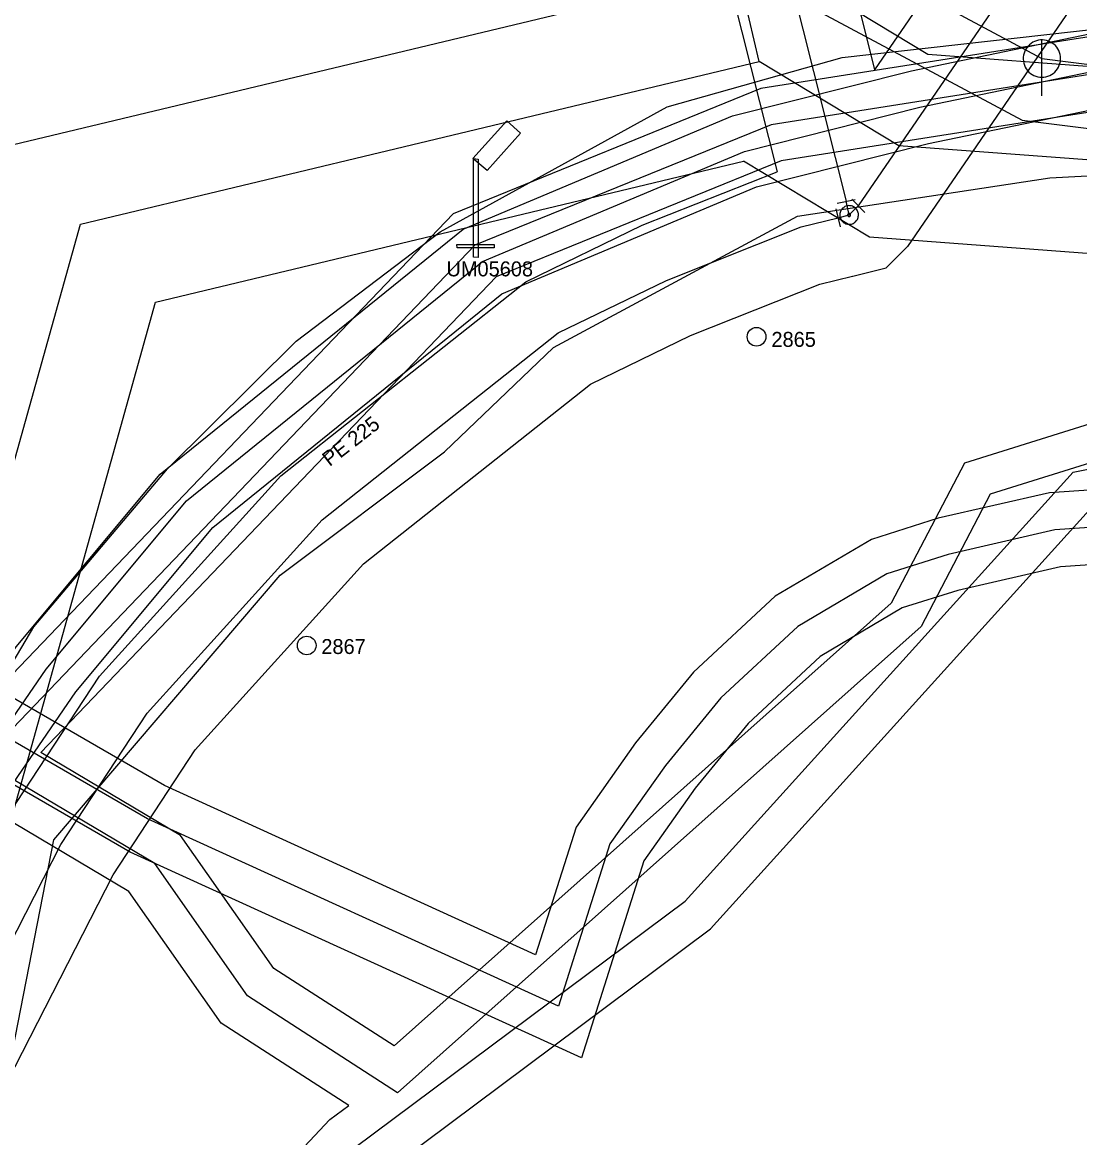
# Model space of a CAD drawing. Extents: x -762993 to -761845, y -975230 to -974501.
# Drawn here: x -762297.6 to -762269.27, y -975033.65 to -975003.77 of the extents above; entities that cross this region are included whole.
import ezdxf

# ---------------------------------------------------------------- set-up
doc = ezdxf.new("R2010")
doc.units = 0
for name, color, linetype in [('IS_CETIN_OP', 7, 'Continuous'), ('IS_CETIN_podzem metalika zam', 7, 'Continuous'), ('IS_CETIN_podzem out of order', 7, 'Continuous'), ('IS_CEZ-D_el vedeni NN podzem', 7, 'Continuous'), ('IS_CEZ-D_OP', 7, 'Continuous'), ('IS_CEZ-T_parovod', 7, 'Continuous'), ('IS_CEZ-T_parovod OP', 7, 'Continuous'), ('IS_DPmUL_OP', 7, 'Continuous'), ('IS_DPmUL_trakce anotace', 7, 'Continuous'), ('IS_DPmUL_trakce stozary', 7, 'Continuous'), ('IS_DPmUL_trakce vedeni', 7, 'Continuous'), ('IS_DPmUL_VO lampy', 7, 'Continuous'), ('IS_DPmUL_VO lampy anotace', 7, 'Continuous'), ('IS_DPmUL_VO vedeni podzem', 7, 'Continuous'), ('IS_SCVK_kanalizace jednotna', 7, 'Continuous'), ('IS_SCVK_kanalizace OP', 7, 'Continuous'), ('IS_SCVK_kanalizace znaky', 7, 'Continuous'), ('IS_SCVK_vodovod anotace', 7, 'Continuous'), ('IS_SCVK_vodovod OP', 7, 'Continuous'), ('IS_SCVK_vodovod privadec', 7, 'Continuous'), ('IS_SCVK_vodovod znaky', 7, 'Continuous')]:
    doc.layers.add(name, color=color, linetype=linetype)

msp = doc.modelspace()

# ---------------------------------------------------------------- linework, layer by layer
at = {"layer": 'IS_CETIN_OP'}
for points in [[(-762333.143, -975068.542), (-762327.185, -975070.257), (-762325.869, -975070.135), (-762319.571, -975070.861), (-762312.657, -975072.148), (-762308.168, -975050.829), (-762306.083, -975041.38), (-762305.481, -975039.001), (-762303.469, -975030.548), (-762300.901, -975025.071), (-762297.758, -975020.495), (-762293.905, -975015.874), (-762285.788, -975009.313), (-762278.568, -975006.279), (-762273.774, -975005.065), (-762267.42, -975003.752), (-762256.598, -975003.579), (-762252.471, -975004.243)], [(-762333.697, -975070.464), (-762327.375, -975072.283), (-762325.891, -975072.145), (-762319.869, -975072.839), (-762311.103, -975074.472), (-762306.212, -975051.251), (-762304.137, -975041.84), (-762303.539, -975039.479), (-762301.571, -975031.212), (-762299.159, -975026.069), (-762296.162, -975021.705), (-762292.495, -975017.306), (-762284.752, -975011.047), (-762277.932, -975008.181), (-762273.326, -975007.015), (-762267.2, -975005.748), (-762256.742, -975005.581), (-762252.789, -975006.217)]]:
    msp.add_lwpolyline(points, dxfattribs=at)
at = {"layer": 'IS_CETIN_podzem metalika zam'}
msp.add_lwpolyline([(-762333.42, -975069.503), (-762327.28, -975071.27), (-762325.88, -975071.14), (-762319.72, -975071.85), (-762311.88, -975073.31), (-762307.19, -975051.04), (-762305.11, -975041.61), (-762304.51, -975039.24), (-762302.52, -975030.88), (-762300.03, -975025.57), (-762296.96, -975021.1), (-762293.2, -975016.59), (-762285.27, -975010.18), (-762278.25, -975007.23), (-762273.55, -975006.04), (-762267.31, -975004.75), (-762256.67, -975004.58), (-762252.63, -975005.23)], dxfattribs=at)
at = {"layer": 'IS_CETIN_podzem out of order'}
for points in [[(-762302.47, -975029.43), (-762301.37, -975026.86), (-762297.29, -975019.96), (-762293.71, -975015.73), (-762290.26, -975012.31), (-762286.4, -975009.38), (-762280.32, -975006.03), (-762275.63, -975004.71), (-762266.26, -975003.66), (-762260.97, -975004.16), (-762250.2, -975005.66)], [(-762314.94, -975039.44), (-762305.75, -975041.48), (-762300.55, -975042.65), (-762300.16, -975040.36), (-762298.53, -975034.72), (-762296.75, -975025.67), (-762290.69, -975018.58), (-762286.29, -975015.28), (-762283.37, -975012.48), (-762276.83, -975008.96), (-762270.07, -975007.94), (-762262.86, -975007.55), (-762258.26, -975007.97), (-762258.37, -975010.02)]]:
    msp.add_lwpolyline(points, dxfattribs=at)
at = {"layer": 'IS_CEZ-D_el vedeni NN podzem'}
msp.add_lwpolyline([(-762266.642, -975017.146), (-762269.935, -975017.363), (-762272.799, -975018.022), (-762274.441, -975018.54), (-762276.825, -975019.952), (-762278.883, -975021.862), (-762280.371, -975023.677), (-762281.857, -975025.781), (-762283.232, -975030.127), (-762294.247, -975025.106), (-762300.557, -975021.459), (-762308.359, -975013.401), (-762309.107, -975012.628), (-762311.684, -975012.049), (-762311.927, -975011.994), (-762311.958, -975011.586), (-762312.434, -975011.429)], dxfattribs=at)
at = {"layer": 'IS_CEZ-D_OP'}
for points in [[(-762210.784, -975019.48), (-762216.14, -975019.152), (-762233.918, -975018.301), (-762252.803, -975016.92), (-762257.758, -975016.55), (-762262.733, -975016.178), (-762264.701, -975016.162), (-762266.671, -975016.146), (-762270.081, -975016.37), (-762273.062, -975017.056), (-762274.852, -975017.621), (-762277.427, -975019.146), (-762279.613, -975021.175), (-762281.167, -975023.071), (-762282.764, -975025.331), (-762283.845, -975028.749), (-762293.788, -975024.216), (-762299.936, -975020.663), (-762307.64, -975012.706), (-762307.985, -975012.349)], [(-762209.615, -975021.555), (-762216.248, -975021.15), (-762234.038, -975020.297), (-762252.951, -975018.914), (-762257.906, -975018.544), (-762262.815, -975018.178), (-762264.717, -975018.162), (-762266.613, -975018.146), (-762269.789, -975018.356), (-762272.536, -975018.988), (-762274.03, -975019.459), (-762276.223, -975020.758), (-762278.153, -975022.549), (-762279.575, -975024.283), (-762280.95, -975026.231), (-762282.619, -975031.505), (-762294.706, -975025.996), (-762301.178, -975022.255), (-762309.078, -975014.096), (-762309.618, -975013.538), (-762311.559, -975013.102)]]:
    msp.add_lwpolyline(points, dxfattribs=at)
at = {"layer": 'IS_CEZ-T_parovod'}
msp.add_line((-762277.86, -975004.82), (-762282.64, -974984.16), dxfattribs=at)
for points in [[(-762300.68, -975025.78), (-762296.04, -975009.18), (-762277.86, -975004.82)], [(-761997.94, -975128.34), (-762040.63, -975080.79), (-762092.91, -975023.16), (-762093.78, -975023), (-762095.1, -975022.88), (-762139.5, -975019.26), (-762139.25, -975015.36), (-762142, -975015.09), (-762142.45, -975019.26), (-762189.8, -975015.24), (-762189.54, -975011.07), (-762194.02, -975010.75), (-762194.39, -975014.25), (-762239.28, -975010.18), (-762239.14, -975006.45), (-762242.94, -975006.24), (-762243.22, -975009.53), (-762252.6, -975008.69), (-762274.12, -975007.08), (-762277.86, -975004.82)]]:
    msp.add_lwpolyline(points, dxfattribs=at)
at = {"layer": 'IS_CEZ-T_parovod OP'}
for points in [[(-762303.135, -975025.276), (-762298.052, -975007.092), (-762280.855, -975002.967)], [(-761996.08, -975126.67), (-762038.774, -975079.115), (-762091.626, -975020.854), (-762093.44, -975020.521), (-762094.885, -975020.389), (-762136.848, -975016.968), (-762136.601, -975013.108), (-762144.22, -975012.36), (-762144.673, -975016.562), (-762187.153, -975012.956), (-762186.891, -975008.753), (-762196.252, -975008.084), (-762196.617, -975011.538), (-762236.693, -975007.904), (-762236.55, -975004.089), (-762245.225, -975003.61), (-762245.498, -975006.816), (-762252.395, -975006.198), (-762273.338, -975004.632), (-762275.663, -975003.227)], [(-762298.225, -975026.284), (-762294.028, -975011.268), (-762278.275, -975007.49)], [(-761999.8, -975130.01), (-762042.486, -975082.465), (-762094.187, -975025.473), (-762095.315, -975025.371), (-762140.2, -975021.711), (-762140.227, -975021.958), (-762192.447, -975017.524), (-762192.411, -975016.94), (-762241.867, -975012.456), (-762241.856, -975012.162), (-762252.805, -975011.182), (-762274.902, -975009.528), (-762278.275, -975007.49)]]:
    msp.add_lwpolyline(points, dxfattribs=at)
at = {"layer": 'IS_DPmUL_OP'}
for p, q in [((-762286.053, -975008.896), (-762298.867, -975022.284)), ((-762284.903, -975010.588), (-762297.101, -975023.332)), ((-762279.162, -975028.056), (-762268.926, -975016.737)), ((-762288.02, -975034.662), (-762279.162, -975028.056)), ((-762289.356, -975033.164), (-762288.852, -975032.788)), ((-762292.624, -975036.631), (-762289.356, -975033.164))]:
    msp.add_line(p, q, dxfattribs=at)
for points in [[(-762256.705, -975004.005), (-762258.274, -975004.045), (-762266.863, -975003.819), (-762277.81, -975005.544), (-762286.053, -975008.896)], [(-762249.405, -975010.386), (-762248.462, -975009.265), (-762248.373, -975007.579), (-762254.211, -975006.583), (-762258.428, -975006.041), (-762266.733, -975005.823), (-762277.27, -975007.484), (-762284.903, -975010.588)], [(-762249.054, -975010.12), (-762256.278, -975013.401), (-762265.739, -975013.507), (-762272.361, -975015.58), (-762274.321, -975019.33), (-762287.639, -975031.19), (-762290.857, -975029.116), (-762293.355, -975025.555), (-762297.101, -975023.332)], [(-762288.852, -975032.788), (-762292.269, -975030.584), (-762294.745, -975027.055), (-762298.521, -975024.815)]]:
    msp.add_lwpolyline(points, dxfattribs=at)
at = {"layer": 'IS_DPmUL_trakce stozary'}
for centre in [(-762277.928, -975012.193), (-762289.978, -975020.463)]:
    msp.add_circle(centre, 0.25, dxfattribs=at)
at = {"layer": 'IS_DPmUL_trakce vedeni'}
for p, q in [((-762269.448, -975015.823), (-762265.748, -975015.063)), ((-762279.838, -975027.313), (-762269.448, -975015.823)), ((-762288.688, -975033.913), (-762279.838, -975027.313))]:
    msp.add_line(p, q, dxfattribs=at)
at = {"layer": 'IS_DPmUL_VO lampy'}
for points in [[(-762284.618, -975006.412), (-762284.248, -975006.742), (-762285.148, -975007.742), (-762285.528, -975007.422)], [(-762285.508, -975007.422), (-762285.388, -975007.432), (-762285.388, -975010.072), (-762285.508, -975010.062)], [(-762285.958, -975009.722), (-762284.958, -975009.722), (-762284.958, -975009.812), (-762285.948, -975009.812)]]:
    msp.add_lwpolyline(points, close=True, dxfattribs=at)
at = {"layer": 'IS_DPmUL_VO vedeni podzem'}
for points in [[(-762248.64, -975011.03), (-762247.481, -975009.652), (-762247.328, -975006.743), (-762254.063, -975005.594), (-762258.351, -975005.043), (-762266.798, -975004.821), (-762277.54, -975006.514), (-762285.478, -975009.742)], [(-762248.64, -975011.03), (-762256.056, -975014.399), (-762265.581, -975014.505), (-762271.667, -975016.41), (-762273.519, -975019.955), (-762287.542, -975032.443), (-762291.563, -975029.85), (-762294.05, -975026.305), (-762311.619, -975015.88), (-762309.396, -975010.853), (-762306.221, -975005.72)], [(-762285.478, -975009.742), (-762299.631, -975024.529)]]:
    msp.add_lwpolyline(points, dxfattribs=at)
at = {"layer": 'IS_SCVK_kanalizace jednotna'}
for points in [[(-762299.318, -974989.209), (-762270.284, -975004.741)], [(-762270.284, -975004.741), (-762233.263, -975009.418)]]:
    msp.add_lwpolyline(points, dxfattribs=at)
at = {"layer": 'IS_SCVK_kanalizace OP'}
for p, q in [((-762300.025, -974990.759), (-762270.809, -975006.388)), ((-762270.809, -975006.388), (-762233.423, -975011.111))]:
    msp.add_line(p, q, dxfattribs=at)
at = {"layer": 'IS_SCVK_kanalizace znaky'}
for points in [[(-762269.784, -975004.741), (-762269.787, -975004.687), (-762269.796, -975004.633), (-762269.811, -975004.579), (-762269.831, -975004.529), (-762269.856, -975004.481), (-762269.888, -975004.436), (-762269.924, -975004.394), (-762269.964, -975004.357), (-762270.008, -975004.324), (-762270.055, -975004.297), (-762270.105, -975004.274), (-762270.157, -975004.258), (-762270.211, -975004.247), (-762270.265, -975004.242), (-762270.32, -975004.243), (-762270.374, -975004.25), (-762270.427, -975004.262), (-762270.479, -975004.28), (-762270.528, -975004.305), (-762270.574, -975004.334), (-762270.617, -975004.369), (-762270.655, -975004.407), (-762270.69, -975004.45), (-762270.72, -975004.496), (-762270.743, -975004.545), (-762270.762, -975004.597), (-762270.775, -975004.65), (-762270.782, -975004.704), (-762270.784, -975004.759), (-762270.779, -975004.814), (-762270.768, -975004.867), (-762270.751, -975004.919), (-762270.729, -975004.969), (-762270.702, -975005.017), (-762270.669, -975005.061), (-762270.632, -975005.101), (-762270.59, -975005.137), (-762270.545, -975005.168), (-762270.497, -975005.194), (-762270.446, -975005.214), (-762270.394, -975005.229), (-762270.34, -975005.238), (-762270.285, -975005.241), (-762270.23, -975005.238), (-762270.176, -975005.229), (-762270.123, -975005.215), (-762270.073, -975005.194), (-762270.024, -975005.168), (-762269.979, -975005.137), (-762269.938, -975005.101), (-762269.9, -975005.062), (-762269.868, -975005.018), (-762269.84, -975004.971), (-762269.818, -975004.921), (-762269.801, -975004.869), (-762269.79, -975004.815), (-762269.785, -975004.76), (-762269.784, -975004.741)], [(-762270.284, -975005.741), (-762270.284, -975004.241)]]:
    msp.add_lwpolyline(points, dxfattribs=at)
at = {"layer": 'IS_SCVK_vodovod OP'}
for p, q in [((-762279.692, -974985.479), (-762274.766, -975005.04)), ((-762282.49, -974987.47), (-762277.378, -975007.772)), ((-762269.402, -974997.215), (-762274.766, -975005.04)), ((-762265.932, -974998.166), (-762273.888, -975009.773)), ((-762274.455, -975010.343), (-762273.888, -975009.773)), ((-762275.348, -975010.569), (-762274.455, -975010.343))]:
    msp.add_line(p, q, dxfattribs=at)
for points in [[(-762300.983, -975030.89), (-762297.958, -975024.984), (-762295.528, -975021.282), (-762290.667, -975015.916), (-762284.106, -975010.718), (-762280.993, -975009.206), (-762277.378, -975007.772)], [(-762298.687, -975033.531), (-762298.612, -975033.335), (-762295.166, -975026.608), (-762292.97, -975023.262), (-762288.455, -975018.278), (-762282.38, -975013.464), (-762279.693, -975012.16), (-762276.236, -975010.788), (-762275.358, -975010.572)]]:
    msp.add_lwpolyline(points, dxfattribs=at)
at = {"layer": 'IS_SCVK_vodovod privadec'}
for points in [[(-762281.341, -974985.482), (-762275.528, -975008.565)], [(-762267.587, -974997.574), (-762275.202, -975008.684)], [(-762300.192, -975032.951), (-762300.086, -975032.676), (-762296.562, -975025.796), (-762294.249, -975022.272), (-762289.561, -975017.097), (-762283.243, -975012.091), (-762280.343, -975010.683), (-762276.729, -975009.249), (-762275.744, -975009.006)]]:
    msp.add_lwpolyline(points, dxfattribs=at)
at = {"layer": 'IS_SCVK_vodovod znaky'}
for points in [[(-762275.772, -975008.618), (-762275.284, -975008.512)], [(-762275.206, -975008.869), (-762275.214, -975008.844), (-762275.224, -975008.82), (-762275.236, -975008.798), (-762275.252, -975008.776), (-762275.269, -975008.756), (-762275.289, -975008.739), (-762275.309, -975008.723), (-762275.332, -975008.71), (-762275.355, -975008.699), (-762275.38, -975008.69), (-762275.406, -975008.685), (-762275.432, -975008.682), (-762275.458, -975008.681), (-762275.484, -975008.684), (-762275.51, -975008.689), (-762275.535, -975008.697), (-762275.559, -975008.707), (-762275.582, -975008.72), (-762275.603, -975008.735), (-762275.623, -975008.752), (-762275.64, -975008.772), (-762275.656, -975008.793), (-762275.669, -975008.815), (-762275.681, -975008.838), (-762275.689, -975008.863), (-762275.694, -975008.889), (-762275.698, -975008.915), (-762275.698, -975008.941), (-762275.695, -975008.967), (-762275.69, -975008.993), (-762275.682, -975009.018), (-762275.672, -975009.042), (-762275.66, -975009.065), (-762275.644, -975009.086), (-762275.627, -975009.106), (-762275.608, -975009.123), (-762275.587, -975009.139), (-762275.564, -975009.153), (-762275.541, -975009.164), (-762275.515, -975009.172), (-762275.49, -975009.177), (-762275.464, -975009.181), (-762275.438, -975009.181), (-762275.412, -975009.178), (-762275.386, -975009.173), (-762275.361, -975009.165), (-762275.337, -975009.155), (-762275.314, -975009.143), (-762275.293, -975009.127), (-762275.273, -975009.11), (-762275.256, -975009.091), (-762275.24, -975009.07), (-762275.226, -975009.048), (-762275.216, -975009.024), (-762275.207, -975008.999), (-762275.202, -975008.973), (-762275.199, -975008.948), (-762275.198, -975008.921), (-762275.201, -975008.895), (-762275.206, -975008.869)], [(-762275.448, -975008.931), (-762275.528, -975008.565)], [(-762275.448, -975008.931), (-762275.202, -975008.684)], [(-762275.378, -975008.507), (-762275.025, -975008.861)], [(-762275.804, -975008.763), (-762275.684, -975009.249)], [(-762275.744, -975009.006), (-762275.448, -975008.931)], [(-762275.408, -975008.921), (-762275.409, -975008.917), (-762275.411, -975008.913), (-762275.413, -975008.909), (-762275.416, -975008.905), (-762275.419, -975008.902), (-762275.422, -975008.9), (-762275.425, -975008.897), (-762275.429, -975008.895), (-762275.432, -975008.893), (-762275.437, -975008.892), (-762275.441, -975008.891), (-762275.446, -975008.89), (-762275.449, -975008.89), (-762275.454, -975008.89), (-762275.458, -975008.891), (-762275.462, -975008.892), (-762275.466, -975008.894), (-762275.47, -975008.896), (-762275.473, -975008.899), (-762275.476, -975008.902), (-762275.479, -975008.905), (-762275.482, -975008.908), (-762275.484, -975008.912), (-762275.486, -975008.916), (-762275.487, -975008.92), (-762275.488, -975008.924), (-762275.489, -975008.929), (-762275.489, -975008.932), (-762275.489, -975008.937), (-762275.488, -975008.941), (-762275.486, -975008.945), (-762275.485, -975008.949), (-762275.483, -975008.953), (-762275.48, -975008.956), (-762275.477, -975008.959), (-762275.475, -975008.963), (-762275.471, -975008.965), (-762275.467, -975008.967), (-762275.463, -975008.969), (-762275.459, -975008.97), (-762275.454, -975008.971), (-762275.45, -975008.972), (-762275.446, -975008.972), (-762275.442, -975008.972), (-762275.438, -975008.971), (-762275.434, -975008.97), (-762275.43, -975008.968), (-762275.426, -975008.966), (-762275.422, -975008.963), (-762275.419, -975008.96), (-762275.416, -975008.958), (-762275.414, -975008.954), (-762275.412, -975008.95), (-762275.41, -975008.946), (-762275.409, -975008.942), (-762275.408, -975008.938), (-762275.407, -975008.933), (-762275.407, -975008.929), (-762275.407, -975008.925), (-762275.408, -975008.921)]]:
    msp.add_lwpolyline(points, dxfattribs=at)

# ---------------------------------------------------------------- texts
at = {"layer": 'IS_DPmUL_trakce anotace'}
for s, p in [('2865', (-762277.529, -975012.463)), ('2867', (-762289.586, -975020.691))]:
    msp.add_text(s, height=0.4, dxfattribs=at).set_placement(p)
at = {"layer": 'IS_DPmUL_VO lampy anotace'}
msp.add_text('UM05608', height=0.4, dxfattribs=at).set_placement((-762286.234, -975010.575))
at = {"layer": 'IS_SCVK_vodovod anotace'}
msp.add_text('PE 225', height=0.4, rotation=38, dxfattribs=at).set_placement((-762289.364, -975015.684))

doc.saveas('drawing.dxf')
